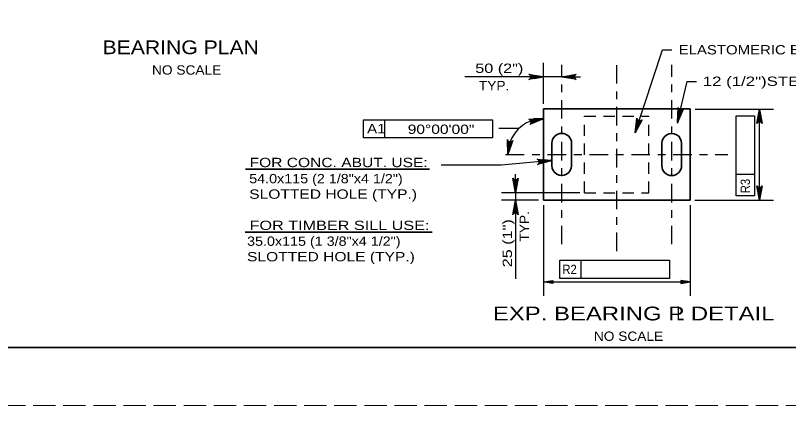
# Model space of a CAD drawing. Extents: x -11 to 79, y -154 to 0.
# Drawn here: x 4.04 to 14, y -154 to -148.97 of the extents above; entities that cross this region are included whole.
import ezdxf
from ezdxf.enums import TextEntityAlignment as Align

# ---------------------------------------------------------------- set-up
doc = ezdxf.new("R2010")
doc.units = 0
doc.header["$LTSCALE"] = 0.048
for name, pattern in [('DOT_DASHED', [7.7, 5, -1.2, 0.3, -1.2]), ('LONG_DASHED', [7.5, 6, -1.5]), ('MEDIUM_DASHED', [4.5, 3, -1.5])]:
    doc.linetypes.add(name, pattern=pattern)
for name, color, linetype, lineweight in [('1', 7, 'Continuous', 25), ('3', 7, 'Continuous', 25), ('4', 7, 'Continuous', 25), ('63', 7, 'LONG_DASHED', 13)]:
    doc.layers.add(name, color=color, linetype=linetype, lineweight=lineweight)

msp = doc.modelspace()

# ---------------------------------------------------------------- hatches: boundary and pattern name
at = {"layer": '4'}
for points in [[(10.72292, -149.74442), (10.72292, -149.78442), (10.84292, -149.76442)], [(11.19908, -149.74442), (11.19908, -149.78442), (11.07908, -149.76442)], [(13.60833, -150.29917), (13.64833, -150.29917), (13.62833, -150.17917)], [(10.72133, -150.29942), (10.7265, -150.33908), (10.84292, -150.30367)], [(12.61617, -150.24817), (12.57717, -150.23908), (12.56933, -150.3605)], [(12.07992, -150.37575), (12.042, -150.36317), (12.02342, -150.48342)], [(10.41792, -150.64767), (10.37825, -150.6425), (10.3825, -150.76408)], [(10.83167, -150.83208), (10.83525, -150.87192), (10.953, -150.84133)], [(10.46233, -151.13617), (10.50233, -151.13617), (10.48233, -151.25617)], [(13.60833, -151.23458), (13.64833, -151.23458), (13.62833, -151.35458)], [(10.46233, -151.47458), (10.50233, -151.47458), (10.48233, -151.35458)], [(10.96292, -152.3875), (10.96292, -152.4275), (10.84292, -152.4075)], [(12.61267, -152.3875), (12.61267, -152.4275), (12.73267, -152.4075)]]:
    msp.add_hatch(color=256, dxfattribs=at).paths.add_polyline_path(points)

# ---------------------------------------------------------------- linework, layer by layer
at = {"layer": '1', "lineweight": 35}
msp.add_lwpolyline([(1.75, -153.25), (33.25, -153.25), (33.25, -132.75), (1.75, -132.75)], close=True, dxfattribs=at)
at = {"layer": '3', "lineweight": 35}
for p, q in [((10.84292, -150.1735), (12.73267, -150.1735)), ((10.84292, -151.35458), (10.84292, -150.1735)), ((12.73267, -151.35458), (12.73267, -150.1735)), ((10.95125, -150.90792), (10.95158, -150.61967)), ((11.20667, -150.61992), (11.20633, -150.90817)), ((12.36892, -150.61992), (12.36917, -150.90817)), ((12.62433, -150.90792), (12.624, -150.61967)), ((10.84292, -151.35458), (12.73267, -151.35458))]:
    msp.add_line(p, q, dxfattribs=at)
at = {"layer": '3', "linetype": 'MEDIUM_DASHED'}
for p, q in [((11.37442, -150.27192), (12.20117, -150.27192)), ((11.37442, -151.25617), (11.37442, -150.27192)), ((12.20117, -151.25617), (12.20117, -150.27192)), ((11.37442, -151.25617), (12.20117, -151.25617))]:
    msp.add_line(p, q, dxfattribs=at)
at = {"layer": '3', "lineweight": 35}
for centre, start, end in [((11.07909, -150.61978), 359.93576, 179.93576), ((12.49641, -150.61978), 0.06424, 180.06424), ((11.07876, -150.908), 179.93576, 359.93576), ((12.49673, -150.908), 180.06424, 0.06424)]:
    msp.add_arc(centre, 0.12756, start, end, dxfattribs=at)
at = {"layer": '4', "linetype": 'DOT_DASHED'}
for p, q in [((11.78775, -152.01058), (11.78775, -149.51758)), ((11.07908, -151.9215), (11.07908, -149.6065)), ((12.49642, -151.9215), (12.49642, -149.6065)), ((10.35642, -150.76408), (13.21917, -150.76408))]:
    msp.add_line(p, q, dxfattribs=at)
at = {"layer": '4'}
for p, q in [((10.84292, -150.111), (10.84292, -149.58442)), ((11.07908, -149.76442), (9.82967, -149.76442)), ((11.07908, -149.76442), (11.31908, -149.76442)), ((12.5725, -150.34683), (12.69483, -149.82367)), ((12.69483, -149.82367), (12.81483, -149.82367)), ((12.80008, -150.17917), (13.80833, -150.17917)), ((13.62833, -151.35458), (13.62833, -150.17917)), ((8.5255, -150.31642), (10.18642, -150.31642)), ((8.5255, -150.54708), (8.5255, -150.31642)), ((8.80108, -150.54708), (8.80108, -150.32567)), ((10.18642, -150.31642), (10.18642, -150.54708)), ((13.32525, -151.2955), (13.32525, -150.26567)), ((13.32525, -150.26567), (13.56142, -150.26567)), ((13.56142, -150.26567), (13.56142, -151.2955)), ((10.5295, -150.42675), (10.27033, -150.42675)), ((10.18642, -150.54708), (8.5255, -150.54708)), ((10.30167, -150.8995), (9.52642, -150.8995)), ((10.95133, -150.8415), (10.30167, -150.8995)), ((10.48233, -151.25617), (10.48233, -151.01617)), ((13.56142, -151.01992), (13.32525, -151.01992)), ((11.31192, -151.25617), (10.30233, -151.25617)), ((10.48233, -151.25617), (10.48233, -152.36833)), ((13.56142, -151.2955), (13.32525, -151.2955)), ((10.78042, -151.35458), (10.30233, -151.35458)), ((10.84292, -151.41708), (10.84292, -152.5875)), ((12.73267, -151.41708), (12.73267, -152.5875)), ((12.79517, -151.35458), (13.80833, -151.35458)), ((11.056, -152.126), (12.46808, -152.126)), ((11.056, -152.36217), (11.056, -152.126)), ((11.33158, -152.36217), (11.33158, -152.126)), ((12.46808, -152.126), (12.46808, -152.36217)), ((10.84292, -152.4075), (12.73267, -152.4075)), ((12.46808, -152.36217), (11.056, -152.36217))]:
    msp.add_line(p, q, dxfattribs=at)
at = {"layer": '4', "lineweight": 35}
for p, q in [((7.00575, -150.95225), (9.37383, -150.95225)), ((7.00125, -151.76525), (9.4075, -151.76525))]:
    msp.add_line(p, q, dxfattribs=at)
at = {"layer": '4'}
for points in [[(12.02342, -150.48333), (12.37592, -149.414), (12.49592, -149.414)], [(10.84292, -149.76442), (10.6565, -149.79933), (10.67083, -149.78942), (10.67825, -149.77692), (10.68042, -149.76442), (10.67825, -149.75192), (10.67083, -149.73942), (10.6565, -149.7295), (10.84292, -149.76442), (10.67083, -149.73942), (10.67825, -149.75192), (10.84292, -149.76442), (10.68042, -149.76442), (10.67825, -149.77692), (10.84292, -149.76442), (10.67083, -149.78942)], [(11.07908, -149.76442), (11.2655, -149.7295), (11.25117, -149.73942), (11.24375, -149.75192), (11.24158, -149.76442), (11.24375, -149.77692), (11.25117, -149.78942), (11.2655, -149.79933), (11.07908, -149.76442), (11.25117, -149.78942), (11.24375, -149.77692), (11.07908, -149.76442), (11.24158, -149.76442), (11.24375, -149.75192), (11.07908, -149.76442), (11.25117, -149.73942)], [(12.5725, -150.34683), (12.58092, -150.15733), (12.58733, -150.17358), (12.59783, -150.18367), (12.6095, -150.18858), (12.62217, -150.18933), (12.636, -150.185), (12.649, -150.17325), (12.5725, -150.34683), (12.636, -150.185), (12.62217, -150.18933), (12.5725, -150.34683), (12.6095, -150.18858), (12.59783, -150.18367), (12.5725, -150.34683), (12.58733, -150.17358)], [(13.62833, -150.17917), (13.66325, -150.36558), (13.65333, -150.35125), (13.64083, -150.34383), (13.62833, -150.34167), (13.61583, -150.34383), (13.60333, -150.35125), (13.59342, -150.36558), (13.62833, -150.17917), (13.60333, -150.35125), (13.61583, -150.34383), (13.62833, -150.17917), (13.62833, -150.34167), (13.64083, -150.34383), (13.62833, -150.17917), (13.65333, -150.35125)], [(10.84292, -150.30367), (10.66825, -150.3775), (10.68008, -150.36475), (10.68467, -150.35092), (10.68417, -150.33825), (10.67933, -150.3265), (10.6695, -150.31583), (10.65333, -150.30925), (10.84292, -150.30367), (10.6695, -150.31583), (10.67933, -150.3265), (10.84292, -150.30367), (10.68417, -150.33825), (10.68467, -150.35092), (10.84292, -150.30367), (10.68008, -150.36475)], [(12.02342, -150.48333), (12.04858, -150.29533), (12.0535, -150.31208), (12.06308, -150.32308), (12.07425, -150.329), (12.08683, -150.33092), (12.101, -150.32775), (12.115, -150.31725), (12.02342, -150.48333), (12.101, -150.32775), (12.08683, -150.33092), (12.02342, -150.48333), (12.07425, -150.329), (12.06308, -150.32308), (12.02342, -150.48333), (12.0535, -150.31208)], [(10.38267, -150.76217), (10.37892, -150.5725), (10.38642, -150.58833), (10.3975, -150.59767), (10.4095, -150.60192), (10.42217, -150.60183), (10.43567, -150.59658), (10.44783, -150.58408), (10.38267, -150.76217), (10.43567, -150.59658), (10.42217, -150.60183), (10.38267, -150.76217), (10.4095, -150.60192), (10.3975, -150.59767), (10.38267, -150.76217), (10.38642, -150.58833)], [(10.95133, -150.8415), (10.76875, -150.89292), (10.78217, -150.88167), (10.78842, -150.86858), (10.7895, -150.85592), (10.78625, -150.84367), (10.77775, -150.83192), (10.76258, -150.82325), (10.95133, -150.8415), (10.77775, -150.83192), (10.78625, -150.84367), (10.95133, -150.8415), (10.7895, -150.85592), (10.78842, -150.86858), (10.95133, -150.8415), (10.78217, -150.88167)], [(10.48233, -151.25617), (10.44742, -151.06975), (10.45733, -151.08408), (10.46983, -151.0915), (10.48233, -151.09367), (10.49483, -151.0915), (10.50733, -151.08408), (10.51725, -151.06975), (10.48233, -151.25617), (10.50733, -151.08408), (10.49483, -151.0915), (10.48233, -151.25617), (10.48233, -151.09367), (10.46983, -151.0915), (10.48233, -151.25617), (10.45733, -151.08408)], [(13.62833, -151.35458), (13.59342, -151.16817), (13.60333, -151.1825), (13.61583, -151.18992), (13.62833, -151.19208), (13.64083, -151.18992), (13.65333, -151.1825), (13.66325, -151.16817), (13.62833, -151.35458), (13.65333, -151.1825), (13.64083, -151.18992), (13.62833, -151.35458), (13.62833, -151.19208), (13.61583, -151.18992), (13.62833, -151.35458), (13.60333, -151.1825)], [(10.48233, -151.35458), (10.51725, -151.541), (10.50733, -151.52667), (10.49483, -151.51925), (10.48233, -151.51708), (10.46983, -151.51925), (10.45733, -151.52667), (10.44742, -151.541), (10.48233, -151.35458), (10.45733, -151.52667), (10.46983, -151.51925), (10.48233, -151.35458), (10.48233, -151.51708), (10.49483, -151.51925), (10.48233, -151.35458), (10.50733, -151.52667)]]:
    msp.add_lwpolyline(points, dxfattribs=at)
for points in [[(10.72292, -149.74442), (10.72292, -149.78442), (10.84292, -149.76442)], [(11.19908, -149.74442), (11.19908, -149.78442), (11.07908, -149.76442)], [(13.60833, -150.29917), (13.64833, -150.29917), (13.62833, -150.17917)], [(10.72133, -150.29942), (10.7265, -150.33908), (10.84292, -150.30367)], [(12.61617, -150.24817), (12.57717, -150.23908), (12.56933, -150.3605)], [(12.07992, -150.37575), (12.042, -150.36317), (12.02342, -150.48342)], [(10.41792, -150.64767), (10.37825, -150.6425), (10.3825, -150.76408)], [(10.83167, -150.83208), (10.83525, -150.87192), (10.953, -150.84133)], [(10.46233, -151.13617), (10.50233, -151.13617), (10.48233, -151.25617)], [(13.60833, -151.23458), (13.64833, -151.23458), (13.62833, -151.35458)], [(10.46233, -151.47458), (10.50233, -151.47458), (10.48233, -151.35458)], [(10.96292, -152.3875), (10.96292, -152.4275), (10.84292, -152.4075)], [(12.61267, -152.3875), (12.61267, -152.4275), (12.73267, -152.4075)]]:
    msp.add_lwpolyline(points, close=True, dxfattribs=at)
msp.add_arc((10.84287, -150.76403), 0.46042, 89.99759, 180.00321, dxfattribs=at)
at = {"layer": '63'}
msp.add_lwpolyline([(0, -154), (34, -154), (34, -132), (0, -132)], close=True, dxfattribs=at)

# ---------------------------------------------------------------- texts
at = {"layer": '4'}
for s, height, width, p in [('BEARING PLAN', 0.1772, 1.15, (6.16937, -149.47083)), ('50 (2")', 0.12, 1.3, (10.27446, -149.71217)), ('TYP.', 0.12, 1.1, (10.20787, -149.93633)), ('A1', 0.12, 1.2, (8.68912, -150.48983)), ('R2', 0.12, 0.9, (11.18004, -152.30492)), ('EXP. BEARING P DETAIL', 0.1772, 1.3, (12.00654, -152.90233)), ('L', 0.1772, 0.75, (12.60767, -152.89983))]:
    msp.add_text(s, height=height, dxfattribs=dict(at, width=width)).set_placement(p, align=Align.CENTER)
for s, width, p in [('ELASTOMERIC BEARING PAD', 1.2, (12.58592, -149.474)), ('NO SCALE', 1.1, (5.79925, -149.73458)), ('12 (1/2")STEEL SOLE P', 1.35, (12.89642, -149.87967)), ('90°00\'00"', 1.25, (9.09442, -150.49867)), ('FOR CONC. ABUT. USE:', 1.25, (7.05642, -150.92692)), ('54.0x115 (2 1/8"x4 1/2")', 1.15, (7.052, -151.13475)), ('SLOTTED HOLE (TYP.)', 1.25, (7.052, -151.33475)), ('FOR TIMBER SILL USE:', 1.3, (7.05633, -151.73725)), ('35.0x115 (1 3/8"x4 1/2")', 1.15, (7.02392, -151.941)), ('SLOTTED HOLE (TYP.)', 1.25, (7.02392, -152.141)), ('NO SCALE', 1.1, (11.49333, -153.16608))]:
    msp.add_text(s, height=0.12, dxfattribs=dict(at, width=width)).set_placement(p)
for s, width, p in [('R3', 0.9, (13.50425, -151.17063)), ('TYP.', 1.1, (10.65717, -151.69004)), ('25 (1")', 1.3, (10.43792, -151.90812))]:
    msp.add_text(s, height=0.12, rotation=90, dxfattribs=dict(at, width=width)).set_placement(p, align=Align.CENTER)

doc.saveas('drawing.dxf')
